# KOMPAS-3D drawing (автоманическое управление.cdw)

Referenced files: САРЗ-4км.cdw
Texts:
  140604.ЭП.ДП.07.25.07 Э1
  Система автоматического управления работой электропривода  гидроразрыхлителя  Структурная схема.
  Текст на чертеже
  Размерные надписи
  Шероховатость
  Линия-выноска #1
  Линия-выноска #2
  Линия-выноска #3
  Отклонения формы и база
  Заголовок таблицы
  Ячейка таблицы
  Стрелка вида
  Обозначение изменения
  Фигурная скобка
  Номер узла
  Марка координационной оси
  VRCB
  Выносная надпись
  Обозначение узла
  Марка/позиционное обозначение с линией-выноской
  Марка/позиционное обозначение на линии
  Марка/позиционное обозначение без линии-выноски
  Исполнительный двигатель
  Манометр
  Вакуумметр
  Микроконтроллер
  Частотный преобразователь
  Земснаряд
  Защита
  Система автоматического
  управления работой электропривода
  гидроразрыхлителя
  Структурная схема.
  Подгаец А.П.
  140604.ЭМ.ДП.07.21.02 Э1-
  Беляков В.Е.
  Руппель А.А.
Dimensions and other numbers on the sheet: 7; 1; 0; 2; 3; 4; 5; 6; 8; 9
